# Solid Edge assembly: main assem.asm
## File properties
Author: Deepak Maini
Template: Normal.asm
Last saved by: Robert a Rhodes jr
Revision: 10
Application: Solid Edge
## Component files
master rod.par
piston.par
piston pin.par
arti subassm.asm
piston pin plug.par
piston ring.par
master rod bearing.par
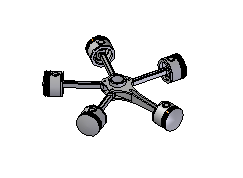
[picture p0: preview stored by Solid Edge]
